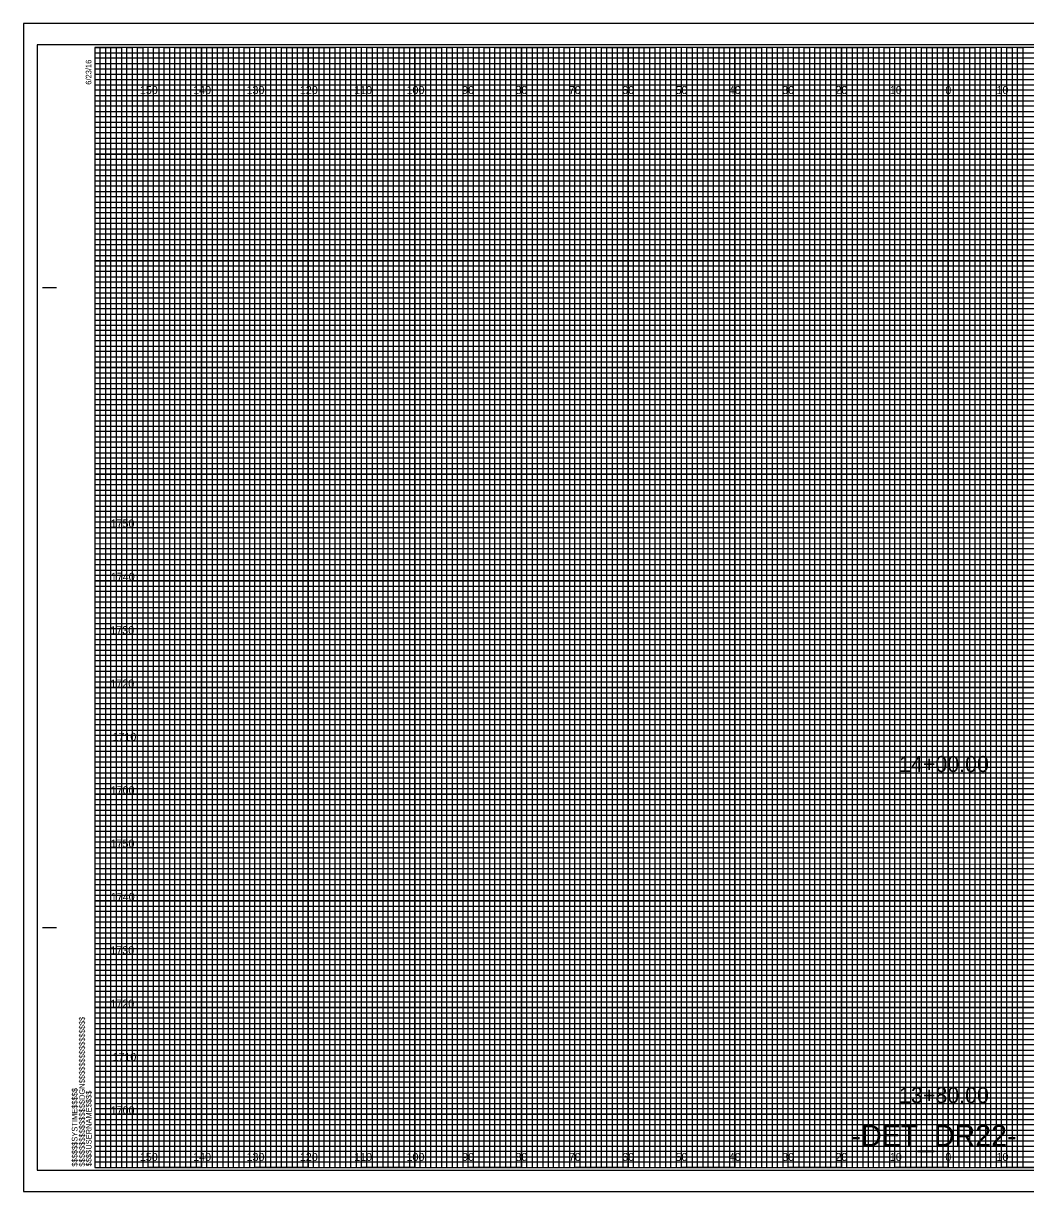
# Model space of a CAD drawing. Extents: x -13 to 323, y -5 to 1314.
# Drawn here: x -13.4 to 174.5, y 1095.5 to 1314.5 of the extents above; entities that cross this region are included whole.
import ezdxf

# ---------------------------------------------------------------- set-up
doc = ezdxf.new("R2010")
doc.units = 0
for name, color, linetype in [('Prop Horizontal Alignment', 7, 'Continuous'), ('Prop XS Alignment Label', 7, 'Continuous'), ('Raster_Level_0', 7, 'Continuous'), ('Scratch_Level_3', 7, 'Continuous'), ('Sheet Cross Section CELL', 7, 'Continuous'), ('Sheet Cross Section Grid Major CELL', 7, 'Continuous'), ('Sheet Cross Section Grid Middle CELL', 7, 'Continuous'), ('Sheet Cross Section Grid Minor 1 CELL', 7, 'Continuous'), ('Sheet Cross Section Grid Minor 2 CELL', 7, 'Continuous'), ('Sheet Cutting Line CELL', 7, 'Continuous'), ('Sheet DOT Grid CELL', 7, 'Continuous'), ('Sheet Plot Border Inside CELL', 7, 'Continuous'), ('Sheet Plot Border Outside CELL', 7, 'Continuous')]:
    doc.layers.add(name, color=color, linetype=linetype)

msp = doc.modelspace()

# ---------------------------------------------------------------- linework, layer by layer
at = {"layer": 'Sheet Cross Section CELL'}
for p, q in [((-9.8, 1265), (-7.3, 1265)), ((-9.7, 1265), (-7.2, 1265)), ((-9.8, 1145), (-7.3, 1145)), ((-9.7, 1145), (-7.2, 1145)), ((0, 1100), (0, 1100)), ((0, 1100), (0, 1100)), ((0, 1100), (0, 1100)), ((0, 1100), (0, 1100)), ((0, 1100), (0, 1100)), ((0, 1100), (0, 1100)), ((0, 1100), (0, 1100))]:
    msp.add_line(p, q, dxfattribs=at)
msp.add_lwpolyline([(320, 1310), (0, 1310), (0, 1100), (320, 1100)], close=True, dxfattribs=at)
at = {"layer": 'Sheet Cross Section Grid Major CELL'}
for p, q in [((10, 1310), (0, 1310)), ((10, 1100), (10, 1310)), ((30, 1310), (20, 1310)), ((20, 1310), (20, 1100)), ((30, 1100), (30, 1310)), ((50, 1310), (40, 1310)), ((40, 1310), (40, 1100)), ((50, 1100), (50, 1310)), ((70, 1310), (60, 1310)), ((60, 1310), (60, 1100)), ((70, 1100), (70, 1310)), ((90, 1310), (80, 1310)), ((80, 1310), (80, 1100)), ((90, 1100), (90, 1310)), ((110, 1310), (100, 1310)), ((100, 1310), (100, 1100)), ((110, 1100), (110, 1310)), ((130, 1310), (120, 1310)), ((120, 1310), (120, 1100)), ((130, 1100), (130, 1310)), ((150, 1310), (140, 1310)), ((140, 1310), (140, 1100)), ((150, 1100), (150, 1310)), ((170, 1310), (160, 1310)), ((160, 1310), (160, 1100)), ((170, 1100), (170, 1310)), ((20, 1100), (10, 1100)), ((40, 1100), (30, 1100)), ((60, 1100), (50, 1100)), ((80, 1100), (70, 1100)), ((100, 1100), (90, 1100)), ((120, 1100), (110, 1100)), ((140, 1100), (130, 1100)), ((160, 1100), (150, 1100)), ((180, 1100), (170, 1100))]:
    msp.add_line(p, q, dxfattribs=at)
for points in [[(0, 1300), (320, 1300), (320, 1290), (0, 1290)], [(0, 1280), (320, 1280), (320, 1270), (0, 1270)], [(0, 1260), (320, 1260), (320, 1250), (0, 1250)], [(0, 1240), (320, 1240), (320, 1230), (0, 1230)], [(0, 1220), (320, 1220), (320, 1210), (0, 1210)], [(0, 1200), (320, 1200), (320, 1190), (0, 1190)], [(0, 1180), (320, 1180), (320, 1170), (0, 1170)], [(0, 1160), (320, 1160), (320, 1150), (0, 1150)], [(0, 1140), (320, 1140), (320, 1130), (0, 1130)], [(0, 1120), (320, 1120), (320, 1110), (0, 1110)]]:
    msp.add_lwpolyline(points, dxfattribs=at)
at = {"layer": 'Sheet Cross Section Grid Middle CELL'}
for points in [[(0, 1310), (5, 1310), (5, 1100), (15, 1100), (15, 1310), (25, 1310), (25, 1100), (35, 1100), (35, 1310), (45, 1310), (45, 1100), (55, 1100), (55, 1310), (65, 1310), (65, 1100), (75, 1100), (75, 1310), (85, 1310), (85, 1100), (95, 1100), (95, 1310), (105, 1310), (105, 1100), (115, 1100), (115, 1310), (125, 1310), (125, 1100), (135, 1100), (135, 1310), (145, 1310), (145, 1100), (155, 1100), (155, 1310), (165, 1310), (165, 1100), (175, 1100)], [(0, 1305), (275, 1305)], [(0, 1285), (320, 1285), (320, 1295), (0, 1295)], [(0, 1265), (320, 1265), (320, 1275), (0, 1275)], [(0, 1245), (320, 1245), (320, 1255), (0, 1255)], [(0, 1225), (320, 1225), (320, 1235), (0, 1235)], [(0, 1205), (320, 1205), (320, 1215), (0, 1215)], [(0, 1185), (320, 1185), (320, 1195), (0, 1195)], [(0, 1165), (320, 1165), (320, 1175), (0, 1175)], [(0, 1145), (320, 1145), (320, 1155), (0, 1155)], [(0, 1125), (320, 1125), (320, 1135), (0, 1135)], [(0, 1105), (320, 1105), (320, 1115), (0, 1115)]]:
    msp.add_lwpolyline(points, dxfattribs=at)
at = {"layer": 'Sheet Cross Section Grid Minor 1 CELL'}
for p, q in [((0, 1309), (260, 1309)), ((260, 1307.98), (0, 1307.98)), ((0, 1307.98), (0, 1307)), ((0, 1307), (260, 1307)), ((260, 1305.89), (0, 1305.89)), ((0, 1305.89), (0, 1304)), ((0, 1304), (320, 1304))]:
    msp.add_line(p, q, dxfattribs=at)
for points in [[(0, 1303), (270, 1303), (320, 1303), (320, 1302), (0, 1302)], [(0, 1301), (320, 1301), (320, 1299), (0, 1299)], [(0, 1298), (320, 1298), (320, 1297), (0, 1296.98)], [(0, 1296), (320, 1296), (320, 1294), (0, 1294)], [(0, 1293), (320, 1293), (320, 1292), (0, 1292)], [(0, 1291), (320, 1291), (320, 1289), (0, 1289)], [(0, 1288), (320, 1288), (320, 1287), (0, 1287)], [(0, 1286), (320, 1286), (320, 1284), (0, 1284)], [(0, 1283), (320, 1283), (320, 1282), (0, 1282)], [(0, 1281), (320, 1281), (320, 1279), (0, 1279)], [(0, 1278), (320, 1278), (320, 1277), (0, 1277)], [(0, 1276), (320, 1276), (320, 1273.95), (320, 1273), (320, 1272), (0, 1272)], [(0, 1274), (320, 1274), (320, 1273), (0, 1273)], [(0, 1271), (320, 1271), (320, 1269), (0, 1269.03)], [(0, 1269.03), (320, 1269), (320, 1268), (0, 1268)], [(0, 1267), (320, 1267), (320, 1266), (0, 1266)], [(0, 1264), (320, 1264), (320, 1263), (0, 1263)], [(0, 1262), (320, 1262), (320, 1261), (0, 1261)], [(-0.07, 1258.89), (320, 1258.89), (320, 1257.88), (-0.07, 1257.88)], [(0, 1257), (320, 1257), (320, 1256), (0, 1256)], [(0, 1254), (320, 1254), (320, 1253), (0, 1253)], [(0, 1252), (320, 1252), (320, 1251), (0, 1251)], [(0, 1249), (320, 1249), (320, 1248), (0, 1248)], [(0, 1247), (320, 1247), (320, 1246), (0, 1246)], [(0, 1244), (320, 1244), (320, 1243), (0, 1243)], [(0, 1242), (320, 1242), (320, 1241), (0, 1241)], [(0, 1239), (320, 1239), (319.99, 1237.98), (0, 1238)], [(0, 1237), (320, 1237), (320, 1236), (0, 1236)], [(0, 1234), (320, 1234), (320, 1233), (0, 1233)], [(0, 1232), (320, 1232), (320, 1231), (0, 1231)], [(0, 1229), (320, 1229), (320, 1228), (0, 1228)], [(0, 1227), (320, 1227), (320, 1226), (0, 1226)], [(0, 1224), (320, 1224), (320, 1223), (0, 1223)], [(0, 1222), (320, 1222), (320, 1221), (0, 1221)], [(0, 1219), (320, 1219), (320, 1218), (0, 1218)], [(0, 1216.99), (320.07, 1216.91), (320, 1216), (0, 1216)], [(0, 1214), (320, 1214), (320, 1213), (0, 1213)], [(0, 1212), (320, 1212), (320, 1211), (0, 1211)], [(0, 1209), (320, 1209), (320, 1208), (0, 1208)], [(0, 1207), (320, 1207), (320, 1206), (0, 1206)], [(0, 1204), (320, 1204), (320, 1203), (0, 1203)], [(0, 1202), (320, 1202), (320, 1201), (0, 1201)], [(0, 1199), (320, 1199), (320, 1198), (0, 1198)], [(0, 1197), (320, 1197), (320, 1196), (0, 1196)], [(0, 1194), (320, 1194), (320, 1193), (0, 1193)], [(0, 1192), (320, 1192), (320, 1191), (0, 1191)], [(0, 1189), (320, 1189), (320, 1188), (0, 1188)], [(0, 1187), (320, 1187), (320, 1186), (0, 1186)], [(0, 1184), (320, 1184), (320, 1183), (0, 1183)], [(0, 1182), (320, 1182), (320, 1181), (0, 1181)], [(0, 1179), (320, 1179), (319.99, 1177.98), (0, 1178)], [(0, 1177), (320, 1177), (320, 1176), (0, 1176)], [(0, 1174), (320, 1174), (320, 1173), (0, 1173)], [(0, 1172), (320, 1172), (320, 1171), (0, 1171)], [(0, 1169), (320, 1169), (320, 1168), (0, 1168)], [(0, 1167), (320, 1167), (320, 1166), (0, 1166)], [(0, 1164), (320, 1164), (320, 1163), (0, 1163)], [(0, 1162), (320, 1162), (320, 1161), (0, 1161)], [(0, 1159), (320, 1159), (320, 1158), (0, 1158)], [(0, 1156.99), (320.07, 1156.91), (320, 1156), (0, 1156)], [(0, 1154), (320, 1154), (320, 1153), (0, 1153)], [(0, 1152), (320, 1152), (320, 1151), (0, 1151)], [(0, 1149), (320, 1149), (320, 1148), (0, 1148)], [(0, 1147), (320, 1147), (320, 1146), (0, 1146)], [(0, 1144), (320, 1144), (320, 1143), (0, 1143)], [(0, 1142), (320, 1142), (320, 1141), (0, 1141)], [(0, 1139), (320, 1139), (320, 1138), (0, 1138)], [(0, 1137), (320, 1137), (320, 1136), (0, 1136)], [(0, 1134), (320, 1134), (320, 1133), (0, 1133)], [(0, 1132), (320, 1132), (320, 1131), (0, 1131)], [(0, 1129), (320, 1129), (320, 1128), (0, 1128)], [(0, 1127), (320, 1127), (320, 1126), (0, 1126)], [(0, 1124), (320, 1124), (320, 1123), (0, 1123)], [(0, 1122), (320, 1122), (320, 1121), (0, 1121)], [(0, 1119), (320, 1119), (320, 1118), (0, 1118)], [(0, 1117), (320, 1117), (320, 1116), (0, 1116)], [(0, 1114), (320, 1114), (320, 1113), (0, 1113)], [(0, 1112), (320, 1112), (320, 1111), (0, 1111)], [(0, 1109), (320, 1109), (320, 1108), (0, 1108)], [(0, 1107), (320, 1107), (320, 1106), (0, 1106)], [(0, 1104), (320, 1104), (320, 1103), (0, 1103)], [(0, 1102), (320, 1102), (320, 1101), (0, 1101)]]:
    msp.add_lwpolyline(points, dxfattribs=at)
at = {"layer": 'Sheet Cross Section Grid Minor 2 CELL'}
for points in [[(0, 1100), (1, 1100), (1, 1310), (2, 1310), (2, 1100)], [(2, 1100), (3, 1100), (3, 1310), (4, 1310), (4, 1100)], [(5, 1100), (6, 1100), (6, 1310), (7, 1310), (7, 1100)], [(7, 1100), (8, 1100), (8, 1310), (9, 1310), (9, 1100)], [(10, 1100), (11, 1100), (11, 1310), (12, 1310), (12, 1100)], [(12, 1100), (13, 1100), (13, 1310), (14, 1310), (14, 1100)], [(15, 1100), (16, 1100), (16, 1310), (17, 1310), (17, 1100)], [(17, 1100), (18, 1100), (18, 1310), (19, 1310), (19, 1100)], [(20, 1100), (21, 1100), (21, 1310), (22, 1310), (22, 1100)], [(22, 1100), (23, 1100), (23, 1310), (24, 1310), (24, 1100)], [(25, 1100), (26, 1100), (26, 1310), (27, 1310), (27, 1100)], [(27, 1100), (28, 1100), (28, 1310), (29, 1310), (29, 1100)], [(30, 1100), (31, 1100), (31, 1310), (32, 1310), (32, 1100)], [(32, 1100), (33, 1100), (33, 1310), (34, 1310), (34, 1100)], [(35, 1100), (36, 1100), (36, 1310), (37, 1310), (37, 1100)], [(37, 1100), (38, 1100), (38, 1310), (39, 1310), (39, 1100)], [(40, 1100), (41, 1100), (41, 1310), (42, 1310), (42, 1100)], [(42, 1100), (43, 1100), (43, 1310), (44, 1310), (44, 1100)], [(45, 1100), (46, 1100), (46, 1310), (47, 1310), (47, 1100)], [(47, 1100), (48, 1100), (48, 1310), (49, 1310), (49, 1100)], [(50, 1100), (51, 1100), (51, 1310), (52, 1310), (52, 1100)], [(52, 1100), (53, 1100), (53, 1310), (54, 1310), (54, 1100)], [(55, 1100), (56, 1100), (56, 1310), (57, 1310), (57, 1100)], [(57, 1100), (58, 1100), (58, 1310), (59, 1310), (59, 1100)], [(60, 1100), (61, 1100), (61, 1310), (62, 1310), (62, 1100)], [(62, 1100), (63, 1100), (63, 1310), (64, 1310), (64, 1100)], [(65, 1100), (66, 1100), (66, 1310), (67, 1310), (67, 1100)], [(67, 1100), (68, 1100), (68, 1310), (69, 1310), (69, 1100)], [(70, 1100), (71, 1100), (71, 1310), (72, 1310), (72, 1100)], [(72, 1100), (73, 1100), (73, 1310), (74, 1310), (74, 1100)], [(75, 1100), (76, 1100), (76, 1310), (77, 1310), (77, 1100)], [(77, 1100), (78, 1100), (78, 1310), (79, 1310), (79, 1100)], [(80, 1100), (81, 1100), (81, 1310), (82, 1310), (82, 1100)], [(82, 1100), (83, 1100), (83, 1310), (84, 1310), (84, 1100)], [(85, 1100), (86, 1100), (86, 1310), (87, 1310), (87, 1100)], [(87, 1100), (88, 1100), (88, 1310), (89, 1310), (89, 1100)], [(90, 1100), (91, 1100), (91, 1310), (92, 1310), (92, 1100)], [(92, 1100), (93, 1100), (93, 1310), (94, 1310), (94, 1100)], [(95, 1100), (96, 1100), (96, 1310), (97, 1310), (97, 1100)], [(97, 1100), (98, 1100), (98, 1310), (99, 1310), (99, 1100)], [(100, 1100), (101, 1100), (101, 1310), (102, 1310), (102, 1100)], [(102, 1100), (103, 1100), (103, 1310), (104, 1310), (104, 1100)], [(105, 1100), (106, 1100), (106, 1310), (107, 1310), (107, 1100)], [(107, 1100), (108, 1100), (108, 1310), (109, 1310), (109, 1100)], [(110, 1100), (111, 1100), (111, 1310), (112, 1310), (112, 1100)], [(112, 1100), (113, 1100), (113, 1310), (114, 1310), (114, 1100)], [(115, 1100), (116, 1100), (116, 1310), (117, 1310), (117, 1100)], [(117, 1100), (118, 1100), (118, 1310), (119, 1310), (119, 1100)], [(120, 1100), (121, 1100), (121, 1310), (122, 1310), (122, 1100)], [(122, 1100), (123, 1100), (123, 1310), (124, 1310), (124, 1100)], [(125, 1100), (126, 1100), (126, 1310), (127, 1310), (127, 1100)], [(127, 1100), (128, 1100), (128, 1310), (129, 1310), (129, 1100)], [(130, 1100), (131, 1100), (131, 1310), (132, 1310), (132, 1100)], [(132, 1100), (133, 1100), (133, 1310), (134, 1310), (134, 1100)], [(135, 1100), (136, 1100), (136, 1310), (137, 1310), (137, 1100)], [(137, 1100), (138, 1100), (138, 1310), (139, 1310), (139, 1100)], [(140, 1100), (141, 1100), (141, 1310), (142, 1310), (142, 1100)], [(142, 1100), (143, 1100), (143, 1310), (144, 1310), (144, 1100)], [(145, 1100), (146, 1100), (146, 1310), (147, 1310), (147, 1100)], [(147, 1100), (148, 1100), (148, 1310), (149, 1310), (149, 1100)], [(150, 1100), (151, 1100), (151, 1310), (152, 1310), (152, 1100)], [(152, 1100), (153, 1100), (153, 1310), (154, 1310), (154, 1100)], [(155, 1100), (156, 1100), (156, 1310), (157, 1310), (157, 1100)], [(157, 1100), (158, 1100), (158, 1310), (159, 1310), (159, 1100)], [(160, 1100), (161, 1100), (161, 1310), (162, 1310), (162, 1100)], [(162, 1100), (163, 1100), (163, 1310), (164, 1310), (164, 1100)], [(165, 1100), (166, 1100), (166, 1310), (167, 1310), (167, 1100)], [(167, 1100), (168, 1100), (168, 1310), (169, 1310), (169, 1100)], [(170, 1100), (171, 1100), (171, 1310), (172, 1310), (172, 1100)], [(172, 1100), (173, 1100), (173, 1310), (174, 1310), (174, 1100)]]:
    msp.add_lwpolyline(points, dxfattribs=at)
at = {"layer": 'Sheet Cutting Line CELL'}
for p, q in [((323.3, 1314.5), (-13.4, 1314.5)), ((-13.4, 1314.5), (-13.4, 1095.5)), ((-13.4, 1095.5), (323.3, 1095.5))]:
    msp.add_line(p, q, dxfattribs=at)
at = {"layer": 'Sheet DOT Grid CELL'}
for p, q in [((10, 1100), (10, 1310)), ((20, 1100), (20, 1310)), ((30, 1100), (30, 1310)), ((40, 1100), (40, 1310)), ((50, 1100), (50, 1310)), ((60, 1100), (60, 1310)), ((70, 1100), (70, 1310)), ((80, 1100), (80, 1310)), ((90, 1100), (90, 1310)), ((100, 1100), (100, 1310)), ((110, 1100), (110, 1310)), ((120, 1100), (120, 1310)), ((130, 1100), (130, 1310)), ((140, 1100), (140, 1310)), ((150, 1100), (150, 1310)), ((160, 1100), (160, 1310)), ((170, 1100), (170, 1310)), ((0, 1300), (320, 1300)), ((0, 1290), (320, 1290)), ((0, 1280), (320, 1280)), ((0, 1270), (320, 1270)), ((0, 1260), (320, 1260)), ((0, 1250), (320, 1250)), ((0, 1240), (320, 1240)), ((0, 1230), (320, 1230)), ((0, 1220), (320, 1220)), ((0, 1210), (320, 1210)), ((0, 1200), (320, 1200)), ((0, 1190), (320, 1190)), ((0, 1180), (320, 1180)), ((0, 1170), (320, 1170)), ((0, 1160), (320, 1160)), ((0, 1150), (320, 1150)), ((0, 1140), (320, 1140)), ((0, 1130), (320, 1130)), ((0, 1120), (320, 1120)), ((0, 1110), (320, 1110))]:
    msp.add_line(p, q, dxfattribs=at)
at = {"layer": 'Sheet Plot Border Inside CELL'}
msp.add_lwpolyline([(-10.8, 1099.5), (322.4, 1099.5), (322.4, 1310.5), (-10.8, 1310.5)], close=True, dxfattribs=at)
at = {"layer": 'Sheet Plot Border Outside CELL'}
msp.add_lwpolyline([(-13.4, 1095.5), (323.3, 1095.5), (323.3, 1314.5), (-13.4, 1314.5)], close=True, dxfattribs=at)

# ---------------------------------------------------------------- texts
at = {"layer": 'Prop Horizontal Alignment'}
for s, p in [('14+00.00', (150.77, 1174.16)), ('13+80.00', (150.77, 1112.1))]:
    msp.add_text(s, height=3, dxfattribs=at).set_placement(p)
at = {"layer": 'Prop XS Alignment Label'}
msp.add_text('-DET_DR22-', height=4, dxfattribs=at).set_placement((141.87, 1104))
at = {"layer": 'Raster_Level_0'}
for s, p in [('150', (8.44, 1301.25)), ('140', (18.44, 1301.25)), ('130', (28.44, 1301.25)), ('120', (38.44, 1301.25)), ('110', (48.62, 1301.25)), ('100', (58.44, 1301.25)), ('90', (68.86, 1301.25)), ('80', (78.86, 1301.25)), ('70', (88.86, 1301.25)), ('60', (98.86, 1301.25)), ('50', (108.86, 1301.25)), ('40', (118.86, 1301.25)), ('30', (128.86, 1301.25)), ('20', (138.86, 1301.25)), ('10', (149.04, 1301.25)), ('0', (159.45, 1301.25)), ('0', (159.45, 1301.25)), ('10', (169.04, 1301.25)), ('150', (8.44, 1101.25)), ('140', (18.44, 1101.25)), ('130', (28.44, 1101.25)), ('120', (38.44, 1101.25)), ('110', (48.62, 1101.25)), ('100', (58.44, 1101.25)), ('90', (68.86, 1101.25)), ('80', (78.86, 1101.25)), ('70', (88.86, 1101.25)), ('60', (98.86, 1101.25)), ('50', (108.86, 1101.25)), ('40', (118.86, 1101.25)), ('30', (128.86, 1101.25)), ('20', (138.86, 1101.25)), ('10', (149.04, 1101.25)), ('0', (159.45, 1101.25)), ('0', (159.45, 1101.25)), ('10', (169.04, 1101.25))]:
    msp.add_text(s, height=1.5, dxfattribs=at).set_placement(p)
at = {"layer": 'Scratch_Level_3'}
for s, p in [('1750', (2.96, 1220)), ('1740', (3, 1210)), ('1730', (2.92, 1200)), ('1720', (2.93, 1190)), ('1710', (3.31, 1180)), ('1700', (2.98, 1170)), ('1750', (2.96, 1160)), ('1740', (3, 1150)), ('1730', (2.92, 1140)), ('1720', (2.93, 1130)), ('1710', (3.31, 1120)), ('1700', (2.98, 1110))]:
    msp.add_text(s, height=1.5, dxfattribs=at).set_placement(p)
at = {"layer": 'Sheet Cross Section CELL'}
for s, p in [('6/23/16', (-0.65, 1303)), ('$$$$$$$$$$$$$$$$DGN$$$$$$$$$$$$$$$$', (-1.88, 1100.18)), ('$$$$$$SYSTIME$$$$$', (-3.26, 1100.18)), ('$$$$USERNAME$$$$', (-0.62, 1100.23))]:
    msp.add_text(s, height=1.05, rotation=90, dxfattribs=at).set_placement(p)

doc.saveas('drawing.dxf')
